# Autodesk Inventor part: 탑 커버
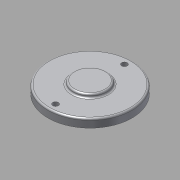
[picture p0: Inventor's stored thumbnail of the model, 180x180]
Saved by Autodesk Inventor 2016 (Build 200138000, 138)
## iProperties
Created: 2017-05
Part Number: 탑 커버
Material: 알루미늄 6061
Document SubType Name: Modeling
Designer: mduedu
Density: 1 g/cm^3
Appearance: 알루미늄 - 평지
Author: mduedu
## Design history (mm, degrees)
sketch "스케치1"
  geometry: C1 r 25 at (0, 0); 1 further point
  constraints: 1 centre point, 1 coincident
  dimensions: "d31" = 50 diameter of C1
extrude "돌출1" new body sketch "스케치1" distance "d2" = 5; taper "d3" = 0 deg
sketch "스케치2"
  geometry: C1 r 10 at (0, 0); 1 further point
  constraints: 1 centre point, 1 coincident
  dimensions: "d5" = 20 diameter of C1
extrude "돌출2" join sketch "스케치2" distance "d6" = 2; taper "d7" = 0 deg
sketch "스케치3"
  geometry: C1 r 16 at (0, 0); 1 further point
  constraints: 1 centre point, 1 coincident
  dimensions: "d32" = 32 diameter of C1
extrude "돌출3" join sketch "스케치3" distance "d10" = 3; taper "d11" = 0 deg
sketch "스케치4"
  geometry: C1 r 16 at (0, 0) reference; C2 r 14 at (0, 0); 1 further point
  constraints: 1 centre point
  dimensions: "d33" = 2 radial gap between concentric circles of C2 C1
extrude "돌출4" cut sketch "스케치4" stored distance "d14" = 2; taper "d15" = 0 deg
chamfer "모따기1" distance "d16" = 1; stored, may be unused: second distance "d17" = 2, angle "d18" = 45 deg
fillet "모깎기3" dims "d19" = 1
fillet "모깎기4" dims "d20" = 1
fillet "모깎기5" dims "d21" = 1
sketch "스케치5" dims "d34" = 41
  geometry: C1 r 25 at (0, 0) reference; 2 further points
  constraints: 2 vertical alignment, 1 coincident, 2 other
hole "구멍2" sketch "스케치5" at (0, 20.5) diameter "d35" = 3.4; stored, may be unused: countersink angle "d39" = 90 deg, drill point angle "d41" = 118 deg; dims "d36" = 6, "d37" = 4, "d38" = 2, "d40" = 8
node "솔리드1"
pattern_circular "원형 패턴1" dims angle "d43" = 360 deg
node "투영된 루프2"
